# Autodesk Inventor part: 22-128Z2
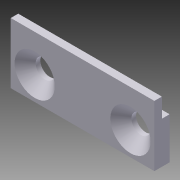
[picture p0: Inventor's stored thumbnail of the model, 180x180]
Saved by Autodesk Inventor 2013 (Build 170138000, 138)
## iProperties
Created: 2004-11
Part Number: 22-128Z2
Document SubType Name: Modeling
Designer: Autodesk, Inc.
Manufacturer: Standard
Standards Organization: Custom
Material: Aluminium - 6061
Description: PARTS BIN, FLAT MOUNT BRACKET
Catalog Web Link: http://www.parker.com/ead/cm1.asp?cmid=809
Vendor: PARKER IPS
Mass: 18.5051 g
Surface Area: 41.2001 cm^2
Volume: 6.82845 cm^3
Density: 2.71 g/cm^3
CAGE: 1LJX3
Dept. ID: Product Design
Description #2: ---
Finish #1: ---
Finish #2: ---
Material ID: ---
Project Number: ---
Description: Parts Bin
Order Number: 22-128Z2
Selection: Flat Mounting Bracket - 60 x 6.4 x 25.4
Supplier: Parker Hannifin Corp., Industrial Profile Systems Div.
Author: Autodesk, Inc.
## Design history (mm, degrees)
feature "Base1"
body "Solid1"
